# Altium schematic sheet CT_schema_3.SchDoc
size 297 x 173 mm
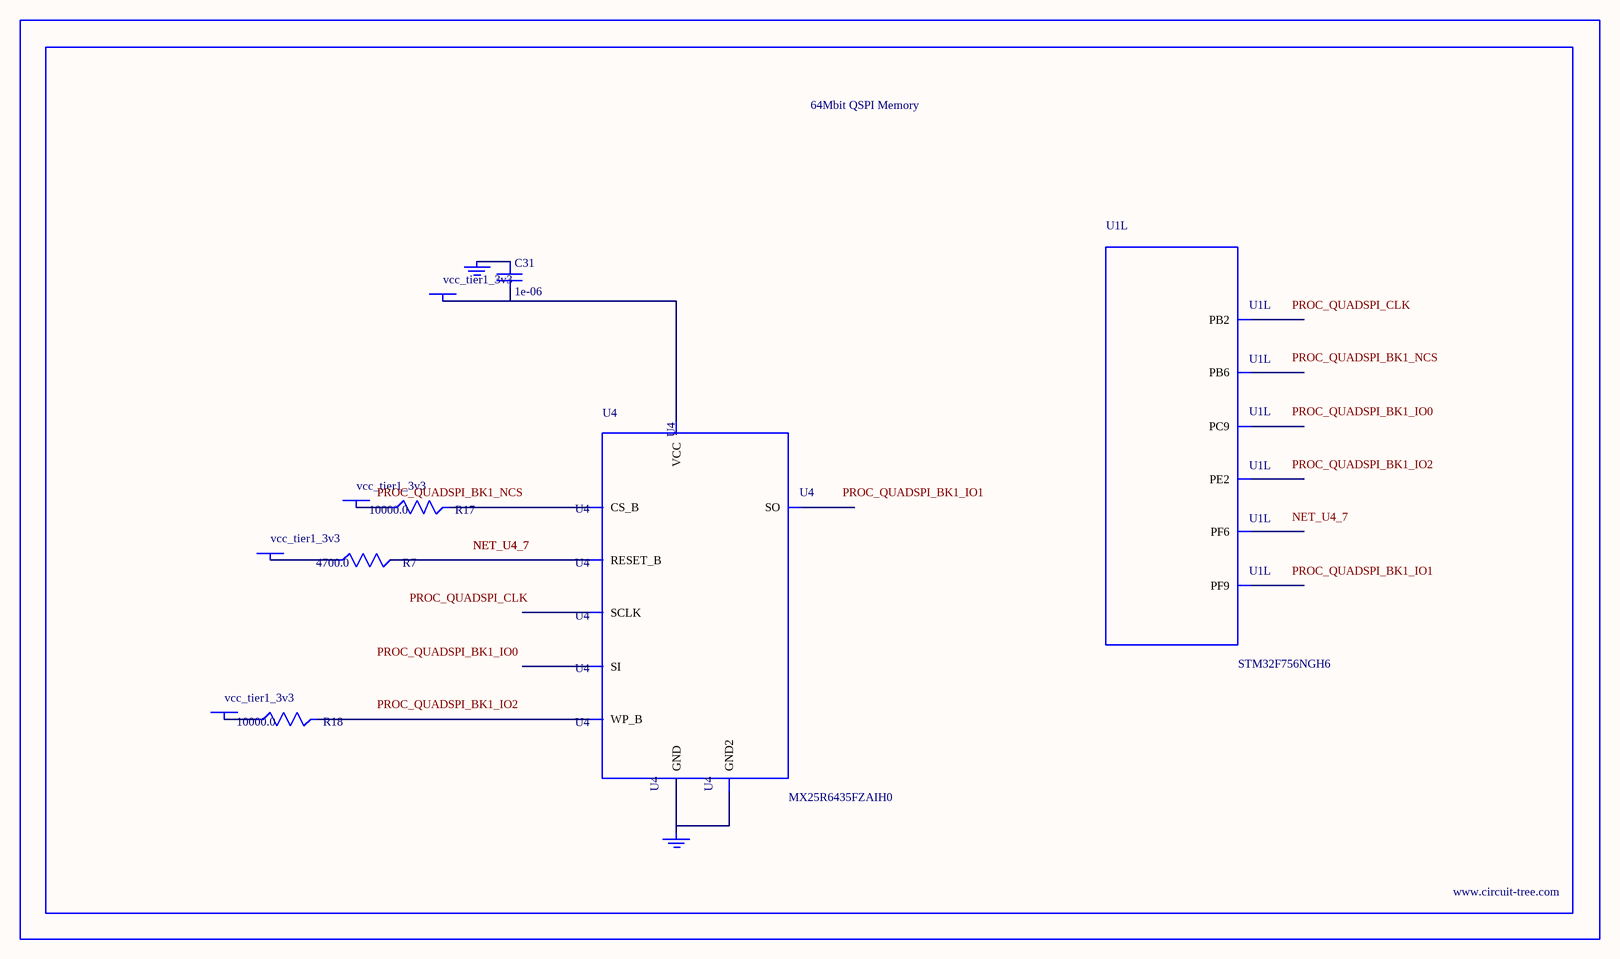
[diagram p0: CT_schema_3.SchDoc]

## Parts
BORDER2  (no value)
C31  1e-06  [C0603]
GND_INSTANCE_2_0  (no value)
GND_INSTANCE_2_1  (no value)
POWER_INSTANCE_2_0  vcc_tier1_3v3
POWER_INSTANCE_2_1  vcc_tier1_3v3
POWER_INSTANCE_2_2  vcc_tier1_3v3
POWER_INSTANCE_2_3  vcc_tier1_3v3
R7  4700.0  [R0603]
R17  10000.0  [R0603]
R18  10000.0  [R0603]
U1  STM32F756NGH6  [TFBGA216]  (part L of 14)
U4  MX25R6435FZAIH0  [WSON-8-PAD]

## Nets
NetC31_1: C31.1 GND_INSTANCE_2_0.0(GND)
NetC31_2: C31.2 POWER_INSTANCE_2_2.0(PWR) U4.8(VCC)
NetGND_INSTANCE_2_1_0: GND_INSTANCE_2_1.0(GND) U4.4(GND) U4.PAD(GND2)
NetPOWER_INSTANCE_2_0_0: POWER_INSTANCE_2_0.0(PWR) R17.1
NetPOWER_INSTANCE_2_1_0: POWER_INSTANCE_2_1.0(PWR) R18.1
NetPOWER_INSTANCE_2_3_0: POWER_INSTANCE_2_3.0(PWR) R7.1
NetR7_2: R7.2 U4.7(RESET_B)
NetR17_2: R17.2 U4.1(CS_B)
NetR18_2: R18.2 U4.3(WP_B)

Not connected (* = marked no-connect by the designer): U1 A3(PE2) B6(PB6) F14(PC9) K2(PF6) L2(PF9) M5(PB2); U4 2(SO) 5(SI) 6(SCLK)

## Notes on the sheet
- Labels drawn without touching a wire or pin: NET_U4_7, PROC_QUADSPI_BK1_IO0, PROC_QUADSPI_BK1_IO1, PROC_QUADSPI_BK1_IO2, PROC_QUADSPI_BK1_NCS, PROC_QUADSPI_CLK

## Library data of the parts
BORDER2 = BORDER_PAGE2
C31 = C0603C105K3RACTU
GND_INSTANCE_2_0 GND_INSTANCE_2_1 = GND
POWER_INSTANCE_2_0-POWER_INSTANCE_2_3 = PWR
R7 = RC0603JR-074K7L
R17 R18 = RC0603JR-0710KL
